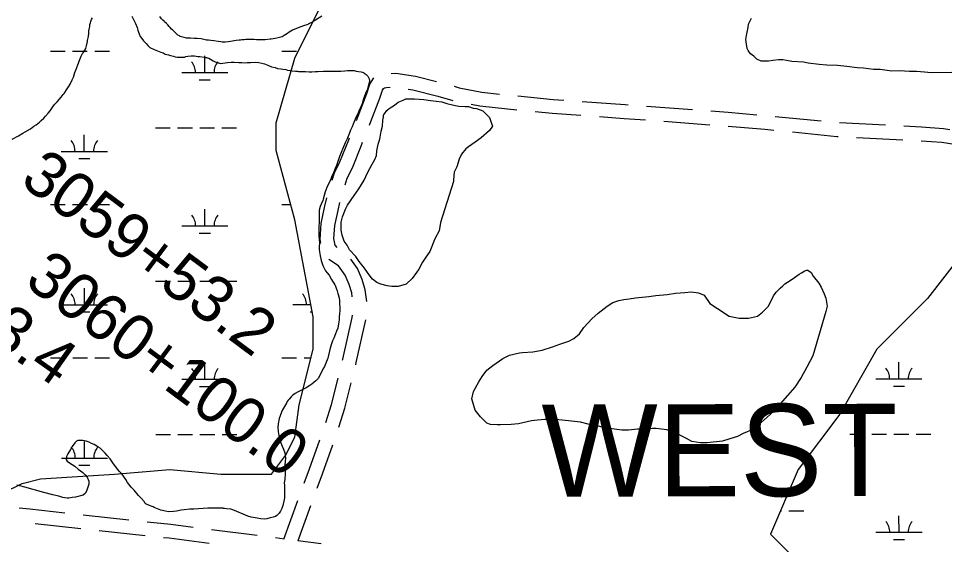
# Model space of a CAD drawing. Extents: x 3279314 to 3317160, y 734079 to 759431.
# Drawn here: x 3296581 to 3298590, y 746467 to 747608 of the extents above; entities that cross this region are included whole.
import ezdxf

# ---------------------------------------------------------------- set-up
doc = ezdxf.new("R2010")
doc.units = 0
for name, color, linetype in [('V-ROAD-CNTR', 7, 'Continuous'), ('V-SITE-VEGE', 7, 'Continuous'), ('V-SURV-IDEN', 7, 'Continuous'), ('V-TOPO-GNAM-IDEN', 7, 'Continuous'), ('V-WETL-SWMP', 7, 'Continuous')]:
    doc.layers.add(name, color=color, linetype=linetype)

msp = doc.modelspace()

# ---------------------------------------------------------------- linework, layer by layer
at = {"layer": 'V-ROAD-CNTR'}
for p, q in [((3297943.5, 747418.2), (3298043.3, 747410.7)), ((3298222.6, 747395.9), (3298322.2, 747386.2)), ((3297980.8, 747385.3), (3298080.5, 747377.9)), ((3298362, 747382.5), (3298461.9, 747377.3)), ((3298399.3, 747350.5), (3298499.2, 747345.4)), ((3297156.9, 746479.1), (3297187.2, 746562.4)), ((3297187.6, 746475.8), (3297215.4, 746552.1)), ((3296616.9, 746513), (3296716.3, 746502.1)), ((3296756, 746497.8), (3296855.4, 746487.1)), ((3296999.4, 746499.9), (3297098.5, 746487.2))]:
    msp.add_line(p, q, dxfattribs=at)
for points in [[(3297389.6, 747489.3), (3297399.7, 747489.6), (3297442.2, 747483.2), (3297487.7, 747471.9)], [(3297314, 747387), (3297317.7, 747396.1), (3297336.5, 747445.4), (3297343.1, 747465.7), (3297351.5, 747479.4)], [(3297342.3, 747376.9), (3297345.6, 747385.2), (3297364.8, 747435.4), (3297370.5, 747453), (3297372.6, 747456.4), (3297375.3, 747457.8), (3297379.2, 747458.9), (3297387, 747459.2)], [(3297426.6, 747455.2), (3297436.3, 747453.8), (3297491, 747440.1), (3297523.5, 747430.8)], [(3297526.2, 747461.2), (3297537.1, 747458.1), (3297586.4, 747448.5), (3297624.7, 747444.5)], [(3297664.5, 747440.4), (3297741.1, 747432.8), (3297764, 747431.1)], [(3297803.9, 747428.3), (3297897.2, 747421.7), (3297903.6, 747421.2)], [(3297562.7, 747422.6), (3297582, 747418.8), (3297642.1, 747412.5), (3297661.9, 747410.5)], [(3297701.7, 747406.5), (3297738.5, 747402.9), (3297801.3, 747398.4)], [(3297841.2, 747395.6), (3297895, 747391.7), (3297940.9, 747388.3)], [(3298083.1, 747407.7), (3298120.9, 747404.9), (3298182.8, 747399.6)], [(3298120.4, 747374.8), (3298200.3, 747368), (3298220, 747366)], [(3298501.8, 747375.3), (3298540.1, 747373.3), (3298587.8, 747369.7), (3298601.4, 747367.5)], [(3297261.1, 747257.6), (3297266.3, 747273.3), (3297278.4, 747297.1), (3297297.3, 747344.9), (3297299.3, 747349.8)], [(3298259.9, 747362.2), (3298356.6, 747352.7), (3298359.4, 747352.6)], [(3297289.3, 747247.5), (3297294.1, 747261.6), (3297305.8, 747284.7), (3297325.2, 747333.9), (3297327.6, 747339.8)], [(3298539.2, 747343.3), (3298584.3, 747339.9), (3298615.9, 747334.8), (3298638.2, 747330.6)], [(3297236.9, 747120.8), (3297235.2, 747129), (3297237.4, 747163.3), (3297244.8, 747198.6), (3297249.8, 747219.2)], [(3297272, 747111.9), (3297268.3, 747116.8), (3297265.4, 747131), (3297267.2, 747159.3), (3297274.1, 747191.9), (3297278.2, 747209.1)], [(3297305.1, 747004.5), (3297303.9, 747013.4), (3297298.1, 747031.5), (3297289.8, 747051.3), (3297275.4, 747071.5), (3297254.3, 747085.5), (3297254.1, 747085.8)], [(3297336.8, 746994.1), (3297333.3, 747020), (3297326.3, 747041.9), (3297316.1, 747066), (3297301.8, 747086.2)], [(3297284.1, 746867), (3297284.6, 746869), (3297304.9, 746959.9), (3297305.2, 746964.7)], [(3297312.5, 746856.7), (3297313.8, 746862.1), (3297334.4, 746954.3)], [(3297247.5, 746732), (3297260.1, 746771), (3297274.4, 746828.2)], [(3297275.7, 746721.7), (3297288.9, 746762.8), (3297302.7, 746817.9)], [(3297200.9, 746600), (3297212.2, 746631.1), (3297234.9, 746694)], [(3297229.1, 746589.7), (3297240.4, 746620.8), (3297263.1, 746683.8)], [(3296582, 746546.5), (3296605.2, 746544.5), (3296681.4, 746536.1)], [(3296721.2, 746531.8), (3296727.4, 746531.1), (3296820.6, 746521)], [(3296860.4, 746516.7), (3296911.1, 746511.2), (3296959.7, 746505)], [(3296895.2, 746482.8), (3296907.6, 746481.4), (3296994.4, 746470.3)], [(3297138.2, 746482.1), (3297157, 746479.7)], [(3297187.2, 746475.8), (3297237.4, 746469.4)]]:
    msp.add_lwpolyline(points, dxfattribs=at)
at = {"layer": 'V-SITE-VEGE'}
for points in [[(3296567.5, 747346.4), (3296581.1, 747354.1), (3296590.5, 747359.3), (3296595.7, 747362.8), (3296606.8, 747369.3), (3296614, 747374.9), (3296619.6, 747377.9), (3296626.4, 747383.1), (3296629.8, 747386.9), (3296635.8, 747392.1), (3296639.6, 747396.4), (3296645.6, 747402.9), (3296649.4, 747408), (3296652.4, 747412.7), (3296656.6, 747418.8), (3296659.6, 747422.6), (3296664.7, 747427.4), (3296673.6, 747437.7), (3296677.9, 747443.3), (3296680, 747445.4), (3296681.3, 747447.6), (3296681.7, 747447.6), (3296685.1, 747453.6), (3296689.4, 747460), (3296692.8, 747466), (3296697.4, 747475.1), (3296700.4, 747481.1), (3296703.4, 747490.9), (3296705.5, 747496.5), (3296707.6, 747501.7), (3296709.7, 747508.1), (3296711, 747511.1), (3296712.6, 747515.8), (3296714.3, 747519.3), (3296715.2, 747522.7), (3296716.9, 747526.6), (3296718.6, 747529.6), (3296719.8, 747532.1), (3296721.5, 747533.9), (3296727.1, 747542.9), (3296728.3, 747548.9), (3296730.8, 747558.3), (3296730.8, 747560.5), (3296732.9, 747569.5), (3296732.9, 747572), (3296733.3, 747574.2), (3296733.3, 747576.7), (3296733.7, 747581.5), (3296735, 747587.9), (3296735.4, 747590.9), (3296735.8, 747593), (3296735.8, 747595.6), (3296737.1, 747599), (3296737.5, 747601.6), (3296739.6, 747606.3), (3296741.7, 747609.8)], [(3296826.9, 747613.6), (3296835.1, 747597.4), (3296838.2, 747588.8), (3296839.9, 747583.3), (3296841.2, 747578.6), (3296842.5, 747574.7), (3296845.1, 747569.2), (3296848.2, 747564.9), (3296852, 747559.8), (3296858.1, 747553.8), (3296861.5, 747550), (3296865.8, 747545.7), (3296875.3, 747541.1), (3296889.4, 747535.1)], [(3297238.9, 747613.2), (3297225.2, 747604.5), (3297220.3, 747602), (3297215.1, 747598.7), (3297212.2, 747597.4), (3297209.8, 747596.1), (3297206.5, 747594.9), (3297199.2, 747592.3), (3297187.8, 747588.1), (3297175.3, 747582.7), (3297168.4, 747578.5), (3297164.3, 747575.6), (3297157.4, 747571.4), (3297152.6, 747568.9), (3297144, 747566.4), (3297137.9, 747564.6), (3297129, 747563.3), (3297126.9, 747563.3), (3297116.3, 747561.9), (3297111.9, 747561.9), (3297107.4, 747562.2), (3297100.8, 747561.7), (3297097.2, 747562.1), (3297091.9, 747562.8), (3297073.9, 747562.6), (3297070.2, 747562.2), (3297065.7, 747562.1), (3297062.9, 747561.3), (3297059.6, 747561.2), (3297053.1, 747560.3), (3297040.9, 747558.1), (3297035.6, 747557.7), (3297029.5, 747556.8), (3297026.6, 747556.7), (3297023, 747557.1), (3297019.7, 747557.9), (3297014.4, 747558.6), (3297005, 747560.1), (3296998, 747560.9), (3296993.1, 747561.6), (3296989, 747561.6), (3296977.2, 747564.3), (3296968.2, 747565), (3296962.1, 747564.9), (3296954.3, 747566), (3296945.7, 747565.9), (3296940, 747567.1), (3296931.8, 747569.4), (3296930.2, 747570.6), (3296926.9, 747572.2), (3296919.4, 747579.5), (3296915.7, 747582.7), (3296913.2, 747585.5), (3296909.9, 747588.7), (3296907.9, 747591.2), (3296904.6, 747594.4), (3296902.1, 747597.6), (3296898, 747601.2), (3296896.7, 747602.9), (3296894.2, 747604.9), (3296891.3, 747607.7), (3296887.6, 747613)], [(3298606, 747490.9), (3298561.2, 747490.7), (3298546.6, 747491.7), (3298528.9, 747493.7), (3298514.3, 747493.6), (3298492.4, 747494.5), (3298475.7, 747494.4), (3298450.7, 747497.5), (3298436.1, 747497.4), (3298414.2, 747500.4), (3298400.6, 747501.4), (3298377.7, 747504.4), (3298357.9, 747506.4), (3298335, 747507.3), (3298318.3, 747508.3), (3298294.3, 747511.3), (3298283.9, 747513.3), (3298258.9, 747515.3), (3298247.4, 747517.3), (3298239.1, 747518.3), (3298229.7, 747518.3), (3298217.2, 747517.2), (3298207.8, 747516.1), (3298192.2, 747516), (3298182.8, 747520.1), (3298176.5, 747526.4), (3298169.2, 747531.5), (3298163.9, 747538.8), (3298161.8, 747543), (3298160.7, 747552.3), (3298158.6, 747562.7), (3298160.6, 747571.1), (3298161.6, 747578.4), (3298163.7, 747588.8), (3298164.7, 747596.1), (3298170.9, 747608.7)], [(3296889.4, 747535.1), (3296894.6, 747533.5), (3296898.9, 747531.3), (3296906.2, 747529.2), (3296910.4, 747528.4), (3296917.3, 747526.3), (3296920.7, 747525.5), (3296925, 747524.6), (3296928, 747524.2), (3296936.2, 747524.3), (3296940.9, 747524.7), (3296944.3, 747525.6), (3296948.6, 747526.5), (3296955.4, 747527.3), (3296961, 747527.4), (3296963.1, 747527), (3296970, 747526.1), (3296974.3, 747525.7), (3296983.7, 747524.5), (3296986.7, 747523.7), (3296988.8, 747523.7), (3296991, 747522.8), (3296994, 747522), (3296997.4, 747520.3), (3297003.4, 747516.5), (3297007.7, 747514.3), (3297011.6, 747512.6), (3297019.3, 747511), (3297029.1, 747511.9), (3297034.7, 747512.8), (3297042, 747513.7), (3297048.8, 747513.3), (3297058.7, 747512.9), (3297065.1, 747512.9), (3297072.8, 747512.5), (3297077.1, 747513), (3297084.4, 747513), (3297095.5, 747513.9), (3297102.4, 747513.1), (3297109.2, 747511.4), (3297114.4, 747509.7), (3297121.7, 747506.8), (3297129.8, 747503.8), (3297138, 747501.7), (3297143.1, 747500), (3297150, 747498.8), (3297154.7, 747498.4), (3297160.7, 747497.6), (3297164.6, 747496.3), (3297170.1, 747495.5), (3297174.4, 747494.6), (3297181.7, 747493.8), (3297186, 747493.8), (3297188.1, 747493.4), (3297199.3, 747493.5), (3297203.5, 747493.1), (3297211.3, 747492.7), (3297217.3, 747492.7), (3297225.4, 747493.2), (3297230.1, 747493.2), (3297242.5, 747494.1), (3297280.2, 747494.3), (3297289.2, 747494.8), (3297294.8, 747495.2), (3297300.7, 747495.3), (3297304.2, 747495.7), (3297309.3, 747495.3), (3297313.2, 747494.1), (3297318.7, 747493.7), (3297324.7, 747492.8), (3297326.9, 747492), (3297329.5, 747491.1)], [(3297329.5, 747491.1), (3297331.2, 747489.4), (3297335.5, 747486.5), (3297338.5, 747483.5), (3297342, 747477.1), (3297342.4, 747473.7), (3297341.6, 747468.5), (3297339.5, 747461.2), (3297337.4, 747453.1), (3297334.8, 747447.9), (3297330.6, 747437.6), (3297329.3, 747433.8), (3297326.4, 747423), (3297323.8, 747416.6), (3297319.6, 747407.6), (3297317.1, 747401.6), (3297312.8, 747393.4), (3297307.3, 747379.3), (3297304.8, 747373.2), (3297301.4, 747366), (3297298.5, 747358.2), (3297293.8, 747347.1), (3297290, 747338.9), (3297284.5, 747326), (3297281.1, 747317.5), (3297277.3, 747309.3), (3297270.5, 747289.6), (3297268, 747282.7), (3297264.2, 747273.3), (3297261.7, 747267.7), (3297257.9, 747258.2), (3297254.9, 747251.8), (3297251.5, 747245.4), (3297246.4, 747232.5), (3297244.3, 747224.3), (3297241.8, 747216.2), (3297241, 747213.6), (3297237.6, 747205.9), (3297235.5, 747200.3), (3297233.4, 747192.2), (3297233.4, 747174.6), (3297233, 747167.3), (3297232.7, 747155.3), (3297232.7, 747147.6), (3297232.8, 747136.1), (3297233.7, 747121.9), (3297233.3, 747112.5), (3297233.4, 747107.8), (3297233.8, 747101.8), (3297235.6, 747093.7), (3297236.9, 747086.8), (3297237.8, 747083), (3297239.1, 747078.7), (3297241.2, 747072.3), (3297243.4, 747068), (3297247.3, 747061.2), (3297250.7, 747056.9), (3297254.6, 747051.4), (3297260.2, 747042.4), (3297262.4, 747038.6), (3297265.4, 747033.9), (3297267.2, 747030.5), (3297268.5, 747027.5), (3297269.8, 747023.6), (3297272.4, 747017.2), (3297273.7, 747011.6), (3297276.7, 747002.2), (3297277.6, 746996.2), (3297277.6, 746990.2), (3297278.1, 746981.3), (3297278.1, 746975.3), (3297277.3, 746967.1), (3297276.9, 746962), (3297276.5, 746954.3), (3297275.3, 746946.1), (3297273.6, 746936.3), (3297271.1, 746930.3), (3297269, 746924.3), (3297264.7, 746915.2), (3297262.2, 746909.2), (3297259.3, 746900.6), (3297258, 746895.1), (3297255.9, 746887.4), (3297253, 746874.5), (3297252.1, 746871.5), (3297250.9, 746868.1), (3297244.9, 746853.5), (3297241.5, 746847.9), (3297238.6, 746841), (3297230.9, 746827.7), (3297225.8, 746822.1), (3297222.4, 746819.1), (3297217.3, 746815.2), (3297213, 746812.2), (3297205.3, 746807.4), (3297198.1, 746803.5), (3297187.4, 746798.4), (3297181.4, 746794.9), (3297176.3, 746791), (3297172.5, 746787.6), (3297167.8, 746782.8)], [(3298317.4, 747034.1), (3298322.7, 747025.8), (3298329, 747011.3), (3298332.2, 747001.9), (3298335.4, 746984.2), (3298333.4, 746975.9), (3298332.3, 746972.7), (3298304.6, 746876.7), (3298291.2, 746851.6), (3298278.8, 746829.7), (3298265.4, 746808.8), (3298233.2, 746772.2), (3298211.5, 746749.1), (3298185.5, 746726.1), (3298174.1, 746716.7), (3298153.3, 746708.2), (3298140.8, 746701.9), (3298124.2, 746696.6), (3298108.6, 746691.3), (3298075.3, 746688), (3298060.7, 746688), (3298041.9, 746691), (3298030.4, 746697.2), (3298002.2, 746711.7), (3297987.6, 746715.8), (3297964.7, 746718.8), (3297956.3, 746718.7), (3297941.7, 746717.6), (3297924, 746717.5), (3297904.2, 746715.4), (3297889.6, 746715.3), (3297874, 746717.3), (3297850, 746721.4), (3297836.5, 746724.4), (3297816.6, 746728.5), (3297799.9, 746732.6), (3297773.9, 746735.6), (3297753, 746737.6), (3297733.2, 746738.5), (3297722.8, 746738.5), (3297707.2, 746737.3), (3297693.6, 746735.2), (3297665.5, 746728.8), (3297649.9, 746727.7), (3297627, 746726.5), (3297619.7, 746726.5), (3297605.1, 746727.5), (3297596.7, 746730.6), (3297583.1, 746744), (3297571.6, 746758.6), (3297564.2, 746783.6), (3297568.3, 746799.2), (3297579.6, 746820.1), (3297586.9, 746831.6), (3297597.2, 746845.2), (3297609.7, 746855.7), (3297631.5, 746870.4), (3297646.1, 746877.7), (3297667.9, 746883), (3297674.2, 746884.1), (3297697.1, 746885.3), (3297716.9, 746888.5), (3297739.8, 746895.9), (3297755.4, 746902.2), (3297775.1, 746908.6), (3297785.5, 746913.8), (3297798, 746924.3), (3297807.3, 746937.9), (3297824.9, 746956.7), (3297838.4, 746969.3), (3297858.1, 746984), (3297870.6, 746992.4), (3297883.1, 746996.6), (3297894.5, 746998.8), (3297906, 746999.9), (3297919.5, 747002), (3297948.7, 747005.3), (3297963.3, 747007.4), (3297988.3, 747009.6), (3298006, 747012.8), (3298026.8, 747014), (3298040.3, 747015.1), (3298056, 747013.1), (3298068.5, 747007.9), (3298081.1, 746990.3), (3298097.8, 746978.9), (3298122.9, 746962.3), (3298144.8, 746958.3), (3298164.6, 746958.4), (3298184.4, 746962.6), (3298194.8, 746971), (3298207.2, 746983.6), (3298214.5, 746997.2), (3298218.6, 747006.6), (3298224.8, 747014.9), (3298233.1, 747023.3), (3298239.3, 747028.5), (3298243.5, 747032.7), (3298254.9, 747040.1), (3298264.2, 747046.4), (3298274.6, 747053.7)], [(3298274.6, 747053.7), (3298279.8, 747056.9), (3298287.1, 747061.1), (3298290.2, 747062.1), (3298293.3, 747062.2), (3298300.7, 747057), (3298304.9, 747049.7), (3298317.4, 747034.1)], [(3297167.8, 746782.8), (3297165.7, 746780.3), (3297164, 746777.3), (3297162.3, 746773.8), (3297155.9, 746763.1), (3297153.8, 746759.2), (3297151.7, 746754.5), (3297148.3, 746746.3), (3297146.6, 746740.3), (3297144.1, 746729.2), (3297143.7, 746721), (3297144.6, 746712.5), (3297146.8, 746699.6), (3297150.3, 746688.1), (3297152.9, 746680.4), (3297155.5, 746674.4), (3297158.5, 746665.9), (3297159.4, 746660.7), (3297159.9, 746653.5), (3297159.5, 746648.3), (3297159.1, 746638.9), (3297159.6, 746633.3), (3297159.6, 746621.3), (3297158.4, 746608.5), (3297157.6, 746601.2), (3297158, 746596.1), (3297158.1, 746584.1), (3297157.7, 746578.5), (3297157.7, 746568.7), (3297156.5, 746561.4), (3297154.4, 746551.5), (3297152.3, 746545.1), (3297149.3, 746539.5), (3297146.3, 746535.2), (3297141.2, 746530.5), (3297138.2, 746527.9), (3297133.5, 746526.6), (3297127.1, 746525.2), (3297119.4, 746523.1), (3297114.7, 746522.2), (3297106.6, 746522.6), (3297098.9, 746524.2), (3297086, 746526.8), (3297078.3, 746528.9), (3297068.4, 746532.7), (3297054.7, 746539), (3297045.7, 746542.4), (3297041.4, 746543.7), (3297032, 746544.5), (3297028.1, 746545.7), (3297025.5, 746545.7), (3297024.7, 746546.1), (3296991.7, 746546), (3296981.4, 746545.1), (3296971.1, 746544.6), (3296961.3, 746543.7), (3296952.3, 746543.6), (3296940.7, 746542.7), (3296933.9, 746541.8), (3296923.6, 746539.6), (3296917.2, 746538.7), (3296906.5, 746538.3), (3296899.6, 746539.5), (3296889.8, 746542), (3296875.6, 746547.5), (3296873, 746548.8), (3296868.8, 746550.5), (3296864.9, 746552.2), (3296860.2, 746553.9), (3296857.6, 746555.1), (3296855.5, 746556.4), (3296853.3, 746560.7), (3296846.8, 746567.5), (3296841.2, 746573.9), (3296831.8, 746585), (3296825.3, 746591.8), (3296817.1, 746602), (3296813.6, 746608), (3296808.9, 746615.3), (3296805.9, 746619.5), (3296800.3, 746625.9), (3296796, 746630.6), (3296794.2, 746632.8), (3296787.3, 746642.6), (3296779.6, 746652.8), (3296773.6, 746660.1), (3296769.2, 746665.6), (3296762.4, 746672), (3296758.1, 746676.2), (3296753.3, 746679.2), (3296745.2, 746683.9), (3296739.2, 746686.4), (3296734, 746689), (3296727.6, 746691.1), (3296720.3, 746692.8), (3296716, 746693.2), (3296710, 746692.7), (3296707, 746691.4), (3296702.8, 746688), (3296697.2, 746679.8), (3296693.8, 746673.4)], [(3296693.8, 746673.4), (3296687.9, 746664.3), (3296685.3, 746658.3), (3296684.1, 746651.5), (3296686.3, 746648), (3296691.4, 746644.2), (3296703, 746637), (3296710.3, 746631), (3296720.6, 746623.4), (3296725.8, 746618.3), (3296730.1, 746613.2), (3296733.2, 746604.6), (3296733.2, 746598.2), (3296731.5, 746591.3), (3296728.1, 746582.7), (3296725.2, 746578), (3296721.3, 746574.6), (3296704.6, 746570.2), (3296697.4, 746568.9), (3296690.1, 746568), (3296686.7, 746568), (3296681.1, 746568.8), (3296676.8, 746569.2), (3296672.5, 746570.9), (3296668.7, 746572.2), (3296668.2, 746572.2), (3296664.8, 746573), (3296655.4, 746575.1), (3296635.6, 746580.1), (3296594.9, 746591.9), (3296583.7, 746594.8), (3296577.3, 746596.1)]]:
    msp.add_lwpolyline(points, dxfattribs=at)
msp.add_lwpolyline([(3297496.7, 747165.7), (3297493.7, 747147.9), (3297484.4, 747130.2), (3297473, 747103), (3297464.8, 747090.5), (3297457.5, 747080), (3297449.3, 747064.4), (3297444.1, 747057), (3297434.8, 747044.5), (3297422.3, 747031.9), (3297404.6, 747026.6), (3297391.1, 747026.6), (3297380.7, 747028.6), (3297367.1, 747031.7), (3297358.7, 747035.8), (3297349.3, 747043), (3297344.1, 747049.3), (3297337.8, 747057.6), (3297331.5, 747066.9), (3297320, 747081.5), (3297312.6, 747091.8), (3297299, 747106.4), (3297293.7, 747116.8), (3297287.4, 747125.1), (3297283.2, 747138.6), (3297281.1, 747149), (3297281, 747166.7), (3297284.1, 747178.2), (3297290.2, 747194.9), (3297294.4, 747203.3), (3297308.9, 747224.2), (3297319.2, 747238.8), (3297330.6, 747257.6), (3297337.8, 747273.3), (3297348.1, 747292.1), (3297354.3, 747302.5), (3297357.4, 747310.9), (3297358.4, 747321.3), (3297361.5, 747335.9), (3297364.5, 747346.4), (3297367.6, 747364.1), (3297370.7, 747374.5), (3297371.6, 747388.1), (3297372.6, 747394.3), (3297372.6, 747398.5), (3297374.7, 747401.6), (3297379.9, 747409), (3297385.1, 747413.1), (3297396.5, 747420.5), (3297404.8, 747426.8), (3297415.2, 747431), (3297421.4, 747434.2), (3297440.2, 747434.2), (3297460, 747432.3), (3297474.6, 747430.2), (3297499.6, 747427.2), (3297510.1, 747424.2), (3297525.7, 747420.1), (3297536.1, 747418), (3297549.7, 747417.1), (3297557, 747417.1), (3297567.4, 747414), (3297574.7, 747413), (3297588.3, 747407.9), (3297602.9, 747393.3), (3297606.1, 747382.9), (3297609.3, 747374.6), (3297603.1, 747365.2), (3297584.4, 747349.5), (3297571.9, 747340.1), (3297557.4, 747329.6), (3297551.2, 747325.4), (3297541.8, 747313.9), (3297536.7, 747303.4), (3297531.6, 747286.7), (3297526.4, 747275.2), (3297524.4, 747258.5), (3297524.4, 747254.4)], close=True, dxfattribs=at)
at = {"layer": 'V-WETL-SWMP'}
for p, q in [((3296650.2, 747537.3), (3296682.2, 747537.3)), ((3296698.2, 747537.3), (3296730.2, 747537.3)), ((3296746.2, 747537.3), (3296778.2, 747537.4)), ((3297152.1, 747537.6), (3297184.1, 747537.6)), ((3296985, 747491), (3296985, 747527)), ((3296935, 747491), (3297035, 747491.1)), ((3296973, 747475.6), (3296997, 747475.6)), ((3296878.2, 747370.9), (3296910.2, 747370.9)), ((3296926.2, 747370.9), (3296958.2, 747371)), ((3296974.2, 747371), (3297006.2, 747371)), ((3297022.2, 747371), (3297054.2, 747371)), ((3296723.7, 747320.1), (3296723.7, 747356.1)), ((3296673.7, 747320.1), (3296773.7, 747320.1)), ((3296711.7, 747304.7), (3296735.7, 747304.7)), ((3296650.3, 747204.6), (3296682.3, 747204.6)), ((3296698.3, 747204.6), (3296730.3, 747204.7)), ((3296746.3, 747204.7), (3296778.3, 747204.7)), ((3296985.2, 747158.4), (3296985.2, 747194.4)), ((3297152.2, 747204.9), (3297171.3, 747204.9)), ((3296935.2, 747158.3), (3297035.2, 747158.4)), ((3296973.2, 747142.9), (3296997.2, 747142.9)), ((3296878.4, 747038.2), (3296910.4, 747038.3)), ((3296926.4, 747038.3), (3296958.4, 747038.3)), ((3296974.4, 747038.3), (3297006.4, 747038.3)), ((3297022.4, 747038.3), (3297054.4, 747038.3)), ((3296723.8, 746987.4), (3296723.8, 747023.4)), ((3296673.8, 746987.4), (3296773.8, 746987.4)), ((3297175.8, 746987.6), (3297215.2, 746987.7)), ((3296711.9, 746972), (3296735.9, 746972)), ((3297213.8, 746972.2), (3297218.1, 746972.2)), ((3296650.5, 746872), (3296682.5, 746872)), ((3296698.5, 746872), (3296730.5, 746872)), ((3296746.5, 746872), (3296778.5, 746872)), ((3297152.4, 746872.2), (3297184.4, 746872.2)), ((3297200.4, 746872.2), (3297215.6, 746872.2)), ((3296985.4, 746825.7), (3296985.3, 746861.7)), ((3298491.1, 746826.5), (3298491.1, 746862.5)), ((3296935.4, 746825.7), (3297035.4, 746825.7)), ((3298441.1, 746826.4), (3298541.1, 746826.5)), ((3296973.4, 746810.3), (3296997.4, 746810.3)), ((3298479.1, 746811), (3298503.1, 746811)), ((3296878.6, 746705.6), (3296910.6, 746705.6)), ((3296926.6, 746705.6), (3296958.6, 746705.6)), ((3296974.6, 746705.6), (3297006.6, 746705.6)), ((3297022.6, 746705.6), (3297054.6, 746705.7)), ((3298384.3, 746706.3), (3298416.3, 746706.3)), ((3298432.3, 746706.4), (3298464.3, 746706.4)), ((3298480.3, 746706.4), (3298512.3, 746706.4)), ((3298528.3, 746706.4), (3298560.3, 746706.4)), ((3296724, 746654.7), (3296724, 746690.7)), ((3296674, 746654.7), (3296774, 746654.8)), ((3296712, 746639.3), (3296736, 746639.3)), ((3298233.9, 746540.1), (3298236.4, 746540.1)), ((3298252.4, 746540.1), (3298284.4, 746540.1)), ((3298491.3, 746493.8), (3298491.2, 746529.8)), ((3298441.3, 746493.8), (3298541.3, 746493.8)), ((3298479.3, 746478.3), (3298503.3, 746478.4))]:
    msp.add_line(p, q, dxfattribs=at)
for points in [[(3296548.9, 746579.9), (3296589, 746599.9), (3296629, 746609.9), (3296789.4, 746620), (3296909.6, 746630), (3297019.9, 746620), (3297130.1, 746620), (3297160.1, 746660.1), (3297180.2, 746700.2), (3297190.2, 746770.4), (3297220.3, 746890.7), (3297220.3, 746960.9), (3297180.2, 747171.5), (3297140.1, 747322), (3297140.1, 747382.1), (3297180.2, 747522.5), (3297240.3, 747642.9)], [(3296548.9, 746579.9), (3296589, 746599.9), (3296629, 746609.9), (3296789.4, 746620), (3296909.6, 746630), (3297019.9, 746620), (3297130.1, 746620), (3297160.1, 746660.1), (3297180.2, 746700.2), (3297190.2, 746770.4), (3297220.3, 746890.7), (3297220.3, 746960.9), (3297180.2, 747171.5), (3297140.1, 747322), (3297140.1, 747382.1), (3297180.2, 747522.5), (3297240.3, 747642.9)], [(3298623.2, 747091.3), (3298553, 747001.1), (3298442.8, 746890.7), (3298362.6, 746750.3), (3298272.4, 746630), (3298212.3, 746489.6), (3298282.5, 746419.4)], [(3298623.2, 747091.3), (3298553, 747001.1), (3298442.8, 746890.7), (3298362.6, 746750.3), (3298272.4, 746630), (3298212.3, 746489.6), (3298282.5, 746419.4)]]:
    msp.add_lwpolyline(points, dxfattribs=at)
for centre, start, end in [((3296929.8, 747491.5), 359.2573, 40.801), ((3297040.3, 747491.5), 139.2573, 180.801), ((3296668.4, 747320.5), 359.2573, 40.801), ((3296778.9, 747320.6), 139.2573, 180.801), ((3296930, 747158.8), 359.2573, 40.801), ((3297040.4, 747158.9), 139.2573, 180.801), ((3296668.6, 746987.9), 359.2573, 40.801), ((3296779.1, 746987.9), 139.2573, 180.801), ((3297170.5, 746988.1), 359.2573, 40.801), ((3296930.1, 746826.1), 359.2573, 40.801), ((3297040.6, 746826.2), 139.2573, 180.801), ((3298435.8, 746826.9), 359.2573, 40.801), ((3298546.3, 746827), 139.2573, 180.801), ((3296668.8, 746655.2), 359.2573, 40.801), ((3296779.3, 746655.2), 139.2573, 180.801), ((3298436, 746494.2), 359.2573, 40.801), ((3298546.5, 746494.3), 139.2573, 180.801)]:
    msp.add_arc(centre, 35.2, start, end, dxfattribs=at)

# ---------------------------------------------------------------- texts
at = {"layer": 'V-SURV-IDEN'}
for s, rotation, p in [('3059+53.2', 323.3474, (3296581.3, 747251.2)), ('3062+53.4', 324.796, (3296140.5, 747173.3)), ('3060+100.0', 323.3216, (3296590.9, 747032.2))]:
    msp.add_text(s, height=100, rotation=rotation, dxfattribs=at).set_placement(p)
at = {"layer": 'V-TOPO-GNAM-IDEN'}
msp.add_text('WEST', height=200, rotation=0.1349, dxfattribs=at).set_placement((3297715.8, 746570.8))

doc.saveas('drawing.dxf')
